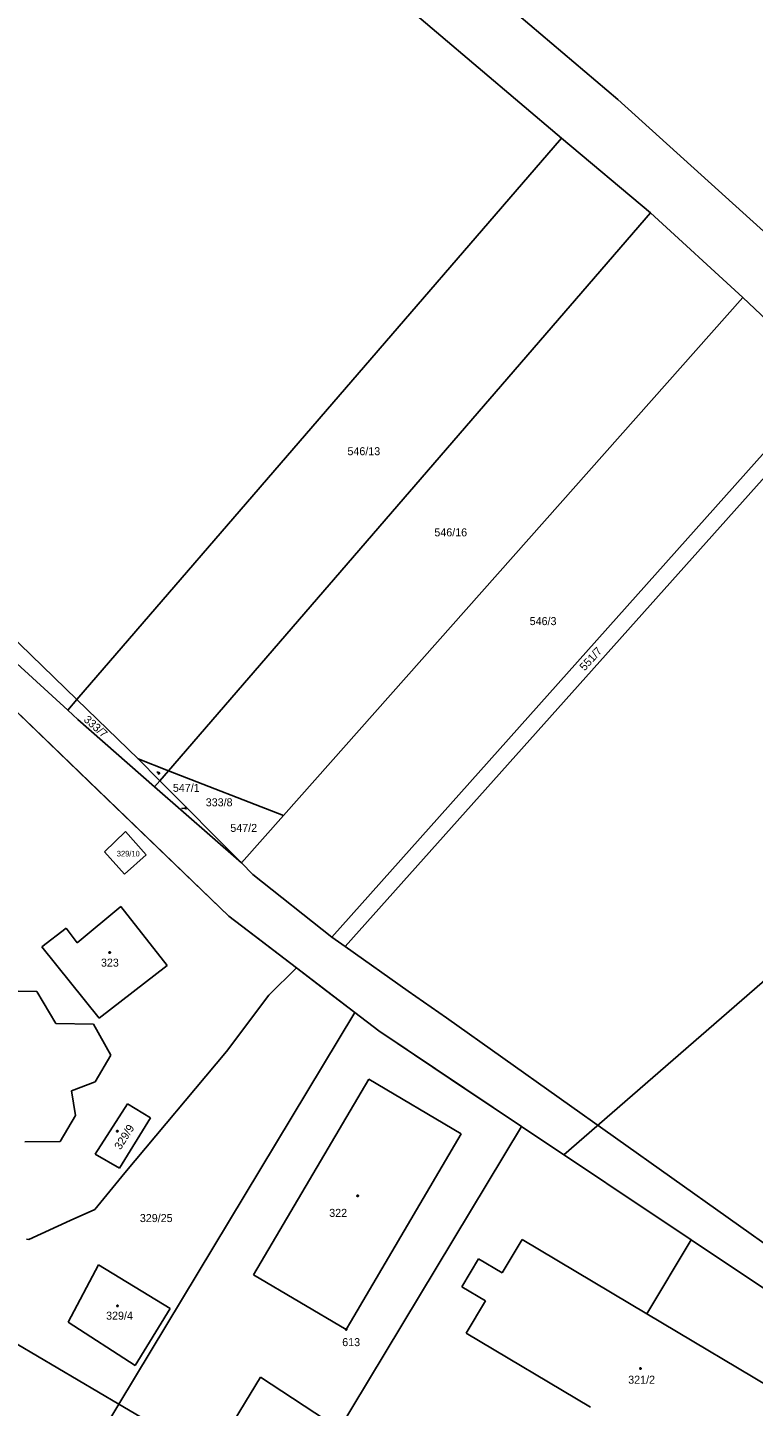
# Model space of a CAD drawing. Extents: x -634640 to -629202, y -1196156 to -1190068.
# Drawn here: x -632220.7 to -632066.6, y -1192574.1 to -1192281.2 of the extents above; entities that cross this region are included whole.
import ezdxf

# ---------------------------------------------------------------- set-up
doc = ezdxf.new("R2010")
doc.units = 0
for name, color, linetype in [('Obvod převzatý', 7, 'Continuous'), ('Obvod šetřený', 7, 'Continuous'), ('Vrstva 1', 7, 'Continuous'), ('Vrstva 2', 7, 'Continuous'), ('Vrstva 5', 7, 'Continuous'), ('Vrstva 7', 7, 'Continuous'), ('Vrstva 8', 7, 'Continuous')]:
    doc.layers.add(name, color=color, linetype=linetype)

msp = doc.modelspace()

# ---------------------------------------------------------------- linework, layer by layer
at = {"layer": 'Obvod převzatý'}
msp.add_lwpolyline([(-632163.67, -1192480.89), (-632170.84, -1192475.395), (-632178.01, -1192469.9), (-632207.785, -1192441.235), (-632237.56, -1192412.57), (-632251.305, -1192399.34), (-632265.05, -1192386.11), (-632272.32, -1192380.04), (-632279.59, -1192373.97)], dxfattribs=at)
at = {"layer": 'Obvod šetřený'}
for points in [[(-632106.873, -1192520.589), (-632039.92, -1192462.45), (-631973.95, -1192405.14), (-631967.895, -1192410.535), (-631961.84, -1192415.93), (-631957.255, -1192420.21), (-631952.67, -1192424.49), (-631949.39, -1192427.55), (-631940.905, -1192417.04), (-631932.42, -1192406.53)], [(-632163.67, -1192480.89), (-632157.475, -1192485.635), (-632151.28, -1192490.38), (-632146.13, -1192494.32), (-632130.985, -1192504.455), (-632115.84, -1192514.59), (-632106.873, -1192520.589)]]:
    msp.add_lwpolyline(points, dxfattribs=at)
at = {"layer": 'Vrstva 1'}
for p, q in [((-632183.08, -1192222.04), (-632095.4, -1192296.52)), ((-632107.36, -1192304.7), (-632188.43, -1192235.84)), ((-632095.4, -1192296.52), (-632041.05, -1192345.67)), ((-632210.25, -1192423.94), (-632107.36, -1192304.7)), ((-632088.46, -1192320.56), (-632107.36, -1192304.7)), ((-632190.81, -1192439.04), (-632088.46, -1192320.56)), ((-632068.9, -1192338.55), (-632088.46, -1192320.56)), ((-632166.4, -1192448.58), (-632068.9, -1192338.55)), ((-632068.9, -1192338.55), (-632050.55, -1192355.95)), ((-632050.55, -1192355.95), (-632156.13, -1192474.41)), ((-632153.33, -1192476.38), (-632047.86, -1192358.33)), ((-632257.63, -1192378.06), (-632210.25, -1192423.94)), ((-632212.16, -1192426.15), (-632261.68, -1192381.3)), ((-632237.56, -1192412.57), (-632178.01, -1192469.9)), ((-632212.16, -1192426.15), (-632210.25, -1192423.94)), ((-632210.05, -1192428.18), (-632212.16, -1192426.15)), ((-632197.24, -1192436.52), (-632210.25, -1192423.94)), ((-632193.76, -1192442.46), (-632210.05, -1192428.18)), ((-632197.24, -1192436.52), (-632192.64, -1192441.17)), ((-632197.24, -1192436.52), (-632190.81, -1192439.04)), ((-632193.76, -1192442.46), (-632192.64, -1192441.17)), ((-632192.64, -1192441.17), (-632190.81, -1192439.04)), ((-632192.64, -1192441.17), (-632175.31, -1192458.63)), ((-632190.81, -1192439.04), (-632166.4, -1192448.58)), ((-632175.31, -1192458.63), (-632193.76, -1192442.46)), ((-632175.31, -1192458.63), (-632166.4, -1192448.58)), ((-632204.42, -1192456.28), (-632199.94, -1192451.95)), ((-632199.94, -1192451.95), (-632195.59, -1192456.89)), ((-632200.14, -1192461), (-632204.42, -1192456.28)), ((-632195.59, -1192456.89), (-632200.14, -1192461)), ((-632172.91, -1192461.05), (-632175.31, -1192458.63)), ((-632156.13, -1192474.41), (-632172.91, -1192461.05)), ((-632210.18, -1192475.59), (-632200.94, -1192467.9)), ((-632200.94, -1192467.9), (-632191.07, -1192480.38)), ((-632178.01, -1192469.9), (-632163.67, -1192480.89)), ((-632217.69, -1192476.47), (-632212.53, -1192472.47)), ((-632212.53, -1192472.47), (-632210.18, -1192475.59)), ((-632205.54, -1192491.6), (-632217.69, -1192476.47)), ((-632153.33, -1192476.38), (-632156.13, -1192474.41)), ((-632139.93, -1192485.83), (-632153.33, -1192476.38)), ((-632191.07, -1192480.38), (-632205.54, -1192491.6)), ((-632169.54, -1192486.69), (-632163.67, -1192480.89)), ((-632163.67, -1192480.89), (-632151.28, -1192490.38)), ((-632226.78, -1192485.81), (-632218.8, -1192485.92)), ((-632218.8, -1192485.92), (-632214.76, -1192492.76)), ((-632178.52, -1192498.64), (-632169.54, -1192486.69)), ((-632131.82, -1192491.55), (-632139.93, -1192485.83)), ((-632201.38, -1192573.54), (-632151.28, -1192490.38)), ((-632151.28, -1192490.38), (-632146.13, -1192494.32)), ((-632214.76, -1192492.76), (-632206.75, -1192492.89)), ((-632206.75, -1192492.89), (-632203.08, -1192499.48)), ((-632057.41, -1192544.4), (-632131.82, -1192491.55)), ((-632146.13, -1192494.32), (-632115.84, -1192514.59)), ((-632203.08, -1192499.48), (-632206.38, -1192505.1)), ((-632200.06, -1192524.41), (-632178.52, -1192498.64)), ((-632206.38, -1192505.1), (-632211.39, -1192507.02)), ((-632172.74, -1192546.13), (-632148.32, -1192504.57)), ((-632148.32, -1192504.57), (-632128.67, -1192516.14)), ((-632211.39, -1192507.02), (-632210.56, -1192512.24)), ((-632199.54, -1192509.82), (-632206.37, -1192520.47)), ((-632194.67, -1192512.74), (-632199.54, -1192509.82)), ((-632252.19, -1192740.91), (-632115.84, -1192514.59)), ((-632210.56, -1192512.24), (-632213.83, -1192517.82)), ((-632201.19, -1192523.48), (-632194.67, -1192512.74)), ((-632115.84, -1192514.59), (-632079.83, -1192538.68)), ((-632128.67, -1192516.14), (-632152.18, -1192556.13)), ((-632213.83, -1192517.82), (-632221.33, -1192517.87)), ((-632206.37, -1192520.47), (-632201.19, -1192523.48)), ((-632206.49, -1192532.24), (-632200.06, -1192524.41)), ((-632220.48, -1192538.61), (-632211.68, -1192534.6)), ((-632211.68, -1192534.6), (-632206.49, -1192532.24)), ((-632221, -1192538.53), (-632220.48, -1192538.61)), ((-632119.96, -1192545.65), (-632115.74, -1192538.59)), ((-632115.74, -1192538.59), (-632089.28, -1192554.37)), ((-632089.28, -1192554.37), (-632079.83, -1192538.68)), ((-632079.83, -1192538.68), (-632043.44, -1192563.03)), ((-632128.52, -1192548.65), (-632125.03, -1192542.74)), ((-632125.03, -1192542.74), (-632119.96, -1192545.65)), ((-632212.11, -1192556.19), (-632205.69, -1192544)), ((-632205.69, -1192544), (-632190.5, -1192553.24)), ((-632153.1, -1192557.7), (-632172.74, -1192546.13)), ((-632123.55, -1192551.63), (-632128.52, -1192548.65)), ((-632127.61, -1192558.51), (-632123.55, -1192551.63)), ((-632190.5, -1192553.24), (-632197.87, -1192565.36)), ((-632089.28, -1192554.37), (-632057.39, -1192573.39)), ((-632231.73, -1192555.7), (-632201.38, -1192573.54)), ((-632197.87, -1192565.36), (-632212.11, -1192556.19)), ((-632152.18, -1192556.13), (-632153.1, -1192557.7)), ((-632127.61, -1192558.51), (-632101.24, -1192574.21)), ((-632206.52, -1192625.73), (-632171.3, -1192567.83)), ((-632171.3, -1192567.83), (-632155.24, -1192578.41)), ((-632210.61, -1192588.86), (-632201.38, -1192573.54)), ((-632201.38, -1192573.54), (-632192.07, -1192579.01))]:
    msp.add_line(p, q, dxfattribs=at)
msp.add_lwpolyline([(-632106.837, -1192520.612), (-632106.838, -1192520.613)], dxfattribs=at)
at = {"layer": 'Vrstva 5'}
for points in [[(-632203.22, -1192477.52), (-632203.13, -1192477.67), (-632203.22, -1192477.82), (-632203.4, -1192477.82), (-632203.49, -1192477.67), (-632203.4, -1192477.52), (-632203.22, -1192477.52)], [(-632201.6, -1192515.47), (-632201.51, -1192515.62), (-632201.6, -1192515.77), (-632201.78, -1192515.77), (-632201.87, -1192515.62), (-632201.78, -1192515.47), (-632201.6, -1192515.47)], [(-632150.56, -1192529.2), (-632150.47, -1192529.35), (-632150.56, -1192529.5), (-632150.74, -1192529.5), (-632150.83, -1192529.35), (-632150.74, -1192529.2), (-632150.56, -1192529.2)], [(-632201.56, -1192552.55), (-632201.47, -1192552.7), (-632201.56, -1192552.85), (-632201.74, -1192552.85), (-632201.83, -1192552.7), (-632201.74, -1192552.55), (-632201.56, -1192552.55)], [(-632090.5, -1192565.84), (-632090.41, -1192565.99), (-632090.5, -1192566.14), (-632090.68, -1192566.14), (-632090.77, -1192565.99), (-632090.68, -1192565.84), (-632090.5, -1192565.84)]]:
    msp.add_lwpolyline(points, dxfattribs=at)
at = {"layer": 'Vrstva 7'}
for p, q in [((-632193.33, -1192439.3), (-632192.88, -1192439.59)), ((-632188.07, -1192447.09), (-632187.13, -1192446.97))]:
    msp.add_line(p, q, dxfattribs=at)
for points in [[(-632192.803, -1192439.747), (-632192.978, -1192439.741), (-632193.055, -1192439.584), (-632192.957, -1192439.433), (-632192.782, -1192439.439), (-632192.705, -1192439.596), (-632192.803, -1192439.747)], [(-632186.97, -1192447.041), (-632187.108, -1192447.149), (-632187.268, -1192447.078), (-632187.29, -1192446.899), (-632187.152, -1192446.791), (-632186.992, -1192446.862), (-632186.97, -1192447.041)]]:
    msp.add_lwpolyline(points, dxfattribs=at)
at = {"layer": 'Vrstva 8'}
msp.add_lwpolyline([(-632153.01, -1192557.55), (-632152.92, -1192557.7), (-632153.01, -1192557.85), (-632153.19, -1192557.85), (-632153.28, -1192557.7), (-632153.19, -1192557.55), (-632153.01, -1192557.55)], dxfattribs=at)

# ---------------------------------------------------------------- texts
at = {"layer": 'Vrstva 2'}
for s, height, p in [('546/13', 1.7, (-632152.823, -1192372.04)), ('546/16', 1.7, (-632134.373, -1192389.27)), ('546/3', 1.7, (-632114.133, -1192408.12)), ('547/1', 0.1, (-632193.316, -1192439.3)), ('547/2', 1.7, (-632177.693, -1192452.04)), ('329/10', 1.19, (-632201.794, -1192457.25)), ('323', 1.7, (-632205.163, -1192480.65)), ('322', 1.7, (-632156.693, -1192533.8)), ('329/25', 1.7, (-632196.903, -1192534.9)), ('329/4', 1.7, (-632204.073, -1192555.63)), ('321/2', 1.7, (-632093.213, -1192569.23))]:
    msp.add_text(s, height=height, dxfattribs=at).set_placement(p)
for s, height, rotation, p in [('551/7', 1.7, 47.67009, (-632102.46, -1192417.954)), ('333/7', 1.7, 318.44994, (-632208.962, -1192428.407)), ('333/8', 0.1, 319.48127, (-632188.059, -1192447.099)), ('329/9', 1.7, 57.75414, (-632201.013, -1192519.689))]:
    msp.add_text(s, height=height, rotation=rotation, dxfattribs=at).set_placement(p)
at = {"layer": 'Vrstva 7'}
for s, p in [('547/1', (-632189.893, -1192443.53)), ('333/8', (-632182.913, -1192446.6))]:
    msp.add_text(s, height=1.7, dxfattribs=at).set_placement(p)
at = {"layer": 'Vrstva 8'}
msp.add_text('613', height=1.7, dxfattribs=at).set_placement((-632153.933, -1192561.25))

doc.saveas('drawing.dxf')
